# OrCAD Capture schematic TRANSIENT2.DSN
size A
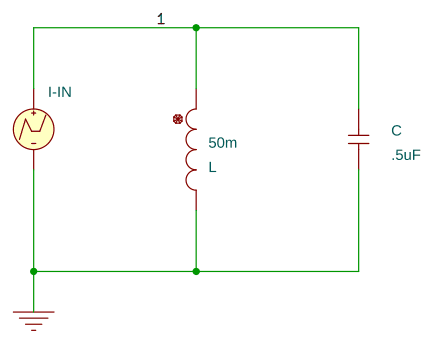
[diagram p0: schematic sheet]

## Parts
C  .5uF  [RAD/CK05]
I-IN  IPWL
L  50m  [DISC/.350x.175/LS.200x.100/.034]

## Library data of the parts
C = C
I-IN = IPWL: I1: 0; I2: 0; I3: 1; I4: 1; I5: 0; T1: 0; T2: 1m; T3: 1.1m; T4: 1.2m; T5: 1.3m
L = L

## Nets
0: C.1 I-IN.2(-) L.2
1: C.2 I-IN.1(+) L.1
